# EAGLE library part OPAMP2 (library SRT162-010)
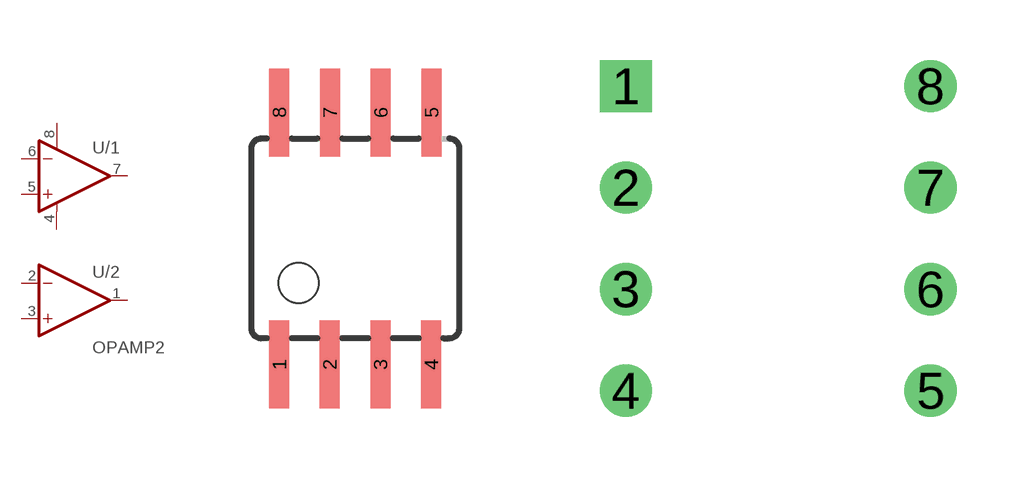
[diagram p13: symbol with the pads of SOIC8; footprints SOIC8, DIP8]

Designator prefix U; gates /1=OPAMP+POWER /2=OPAMP

## OPAMP2  [SOIC8]
1  /2:OUT  pas
2  /2:-IN  in
3  /2:+IN  in
4  /1:V-  pwr
5  /1:+IN  in
6  /1:-IN  in
7  /1:OUT  pas
8  /1:V+  pwr

## OPAMP2DIP  [DIP8]
Pads as for SOIC8

## OPAMP2SSOP8  [SSOP8]
Pads as for SOIC8

## Footprint SOIC8 (pad centres in mm)
smd 0.5 x 2.2: 1 -1.905,-3.154; 2 -0.645,-3.154; 3 0.625,-3.154; 4 1.895,-3.154; 5 1.905,3.154; 6 0.635,3.154; 7 -0.635,3.154; 8 -1.905,3.154

## Footprint DIP8 (pad centres in mm)
drill 0.8 square: 1 -3.81,3.81
drill 0.8 round: 2 -3.81,1.27; 3 -3.81,-1.27; 4 -3.81,-3.81; 5 3.81,-3.81; 6 3.81,-1.27; 7 3.81,1.27; 8 3.81,3.81

## Footprint SSOP8 (pad centres in mm)
smd 0.4 x 1: 1 -0.975,-2.4; 2 -0.325,-2.4; 3 0.325,-2.4; 4 0.975,-2.4; 5 0.975,2.4; 6 0.325,2.4; 7 -0.325,2.4; 8 -0.975,2.4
